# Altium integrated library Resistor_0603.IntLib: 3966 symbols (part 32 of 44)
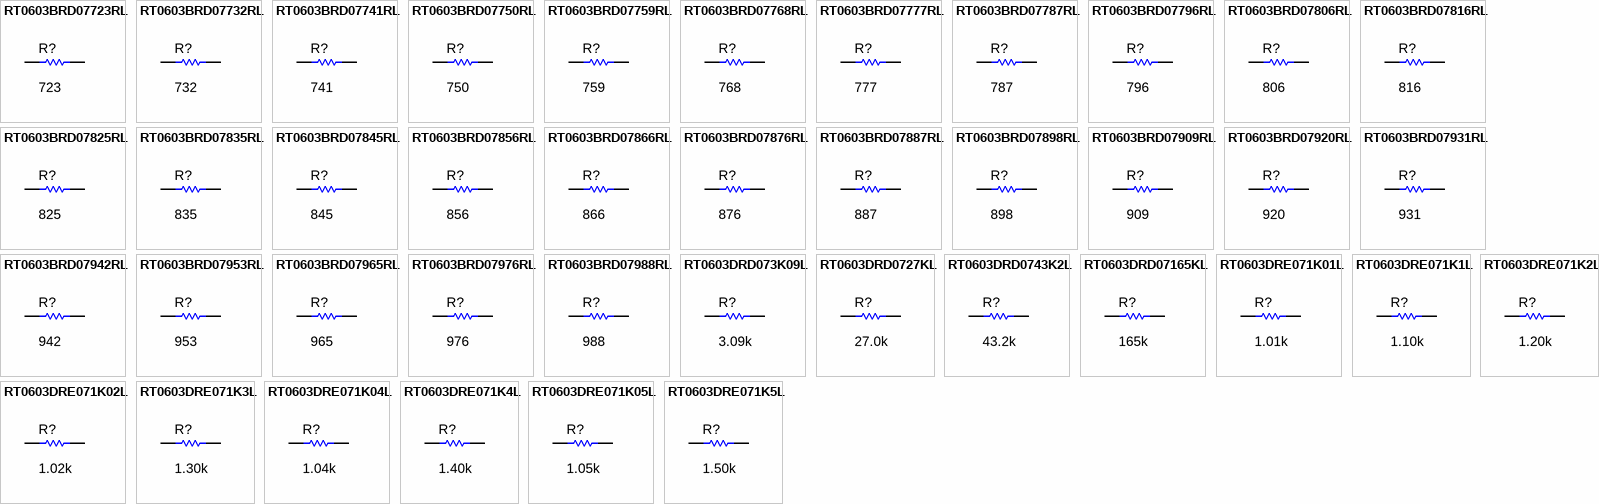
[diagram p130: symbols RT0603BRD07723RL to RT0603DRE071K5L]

## RT0603DRE071K02L
designator R?  ValueDisplayed: 1.02k  (hidden comment: RT0603DRE071K02L)
RES, 1.02 k, 0.5%, 0.1 W, 0603; Manufacturer: Yageo America; CompType: Resistor; Value: 1.02k; Res_ohm: 1020; Value_Code: 1k02; Tolerance_%: 0.5; Power_W: 0.1; Value2: 0.1W; VDC_V: 75; TempCo: 50 ppm/C; SizeArea_mm2: 1.28; SizeX_mm: 1.6; SizeY_mm: 0.8; SizeZ_mm: 1; EIA_Code: E192; U/M: EA; AEC Category: Q200
signal-integrity model Resistor
simulation model Resistor
footprint 0603
footprint 0603M
footprint 0603L
footprint 0603_HV
footprint 0603S
pins: 1, 2

## RT0603DRE071K2L
designator R?  ValueDisplayed: 1.20k  (hidden comment: RT0603DRE071K2L)
RES, 1.20 k, 0.5%, 0.1 W, 0603; Manufacturer: Yageo America; CompType: Resistor; Value: 1.20k; Res_ohm: 1200; Value_Code: 1k20; Tolerance_%: 0.5; Power_W: 0.1; Value2: 0.1W; VDC_V: 75; TempCo: 50 ppm/C; SizeArea_mm2: 1.28; SizeX_mm: 1.6; SizeY_mm: 0.8; SizeZ_mm: 1; EIA_Code: E192; U/M: EA; AEC Category: Q200
signal-integrity model Resistor
simulation model Resistor
footprint 0603
footprint 0603M
footprint 0603L
footprint 0603_HV
footprint 0603S
pins: 1, 2

## RT0603DRE071K3L
designator R?  ValueDisplayed: 1.30k  (hidden comment: RT0603DRE071K3L)
RES, 1.30 k, 0.5%, 0.1 W, 0603; Manufacturer: Yageo America; CompType: Resistor; Value: 1.30k; Res_ohm: 1300; Value_Code: 1k30; Tolerance_%: 0.5; Power_W: 0.1; Value2: 0.1W; VDC_V: 75; TempCo: 50 ppm/C; SizeArea_mm2: 1.28; SizeX_mm: 1.6; SizeY_mm: 0.8; SizeZ_mm: 1; EIA_Code: E192; U/M: EA; AEC Category: Q200
signal-integrity model Resistor
simulation model Resistor
footprint 0603
footprint 0603M
footprint 0603L
footprint 0603_HV
footprint 0603S
pins: 1, 2

## RT0603DRE071K04L
designator R?  ValueDisplayed: 1.04k  (hidden comment: RT0603DRE071K04L)
RES, 1.04 k, 0.5%, 0.1 W, 0603; Manufacturer: Yageo America; CompType: Resistor; Value: 1.04k; Res_ohm: 1040; Value_Code: 1k04; Tolerance_%: 0.5; Power_W: 0.1; Value2: 0.1W; VDC_V: 75; TempCo: 50 ppm/C; SizeArea_mm2: 1.28; SizeX_mm: 1.6; SizeY_mm: 0.8; SizeZ_mm: 1; EIA_Code: E192; U/M: EA; AEC Category: Q200
signal-integrity model Resistor
simulation model Resistor
footprint 0603
footprint 0603M
footprint 0603L
footprint 0603_HV
footprint 0603S
pins: 1, 2

## RT0603DRE071K4L
designator R?  ValueDisplayed: 1.40k  (hidden comment: RT0603DRE071K4L)
RES, 1.40 k, 0.5%, 0.1 W, 0603; Manufacturer: Yageo America; CompType: Resistor; Value: 1.40k; Res_ohm: 1400; Value_Code: 1k40; Tolerance_%: 0.5; Power_W: 0.1; Value2: 0.1W; VDC_V: 75; TempCo: 50 ppm/C; SizeArea_mm2: 1.28; SizeX_mm: 1.6; SizeY_mm: 0.8; SizeZ_mm: 1; EIA_Code: E192; U/M: EA; AEC Category: Q200
signal-integrity model Resistor
simulation model Resistor
footprint 0603
footprint 0603M
footprint 0603L
footprint 0603_HV
footprint 0603S
pins: 1, 2

## RT0603DRE071K05L
designator R?  ValueDisplayed: 1.05k  (hidden comment: RT0603DRE071K05L)
RES, 1.05 k, 0.5%, 0.1 W, 0603; Manufacturer: Yageo America; CompType: Resistor; Value: 1.05k; Res_ohm: 1050; Value_Code: 1k05; Tolerance_%: 0.5; Power_W: 0.1; Value2: 0.1W; VDC_V: 75; TempCo: 50 ppm/C; SizeArea_mm2: 1.28; SizeX_mm: 1.6; SizeY_mm: 0.8; SizeZ_mm: 1; EIA_Code: E192; U/M: EA; AEC Category: Q200
signal-integrity model Resistor
simulation model Resistor
footprint 0603
footprint 0603M
footprint 0603L
footprint 0603_HV
footprint 0603S
pins: 1, 2

## RT0603DRE071K5L
designator R?  ValueDisplayed: 1.50k  (hidden comment: RT0603DRE071K5L)
RES, 1.50 k, 0.5%, 0.1 W, 0603; Manufacturer: Yageo America; CompType: Resistor; Value: 1.50k; Res_ohm: 1500; Value_Code: 1k50; Tolerance_%: 0.5; Power_W: 0.1; Value2: 0.1W; VDC_V: 75; TempCo: 50 ppm/C; SizeArea_mm2: 1.28; SizeX_mm: 1.6; SizeY_mm: 0.8; SizeZ_mm: 1; EIA_Code: E192; U/M: EA; AEC Category: Q200
signal-integrity model Resistor
simulation model Resistor
footprint 0603
footprint 0603M
footprint 0603L
footprint 0603_HV
footprint 0603S
pins: 1, 2

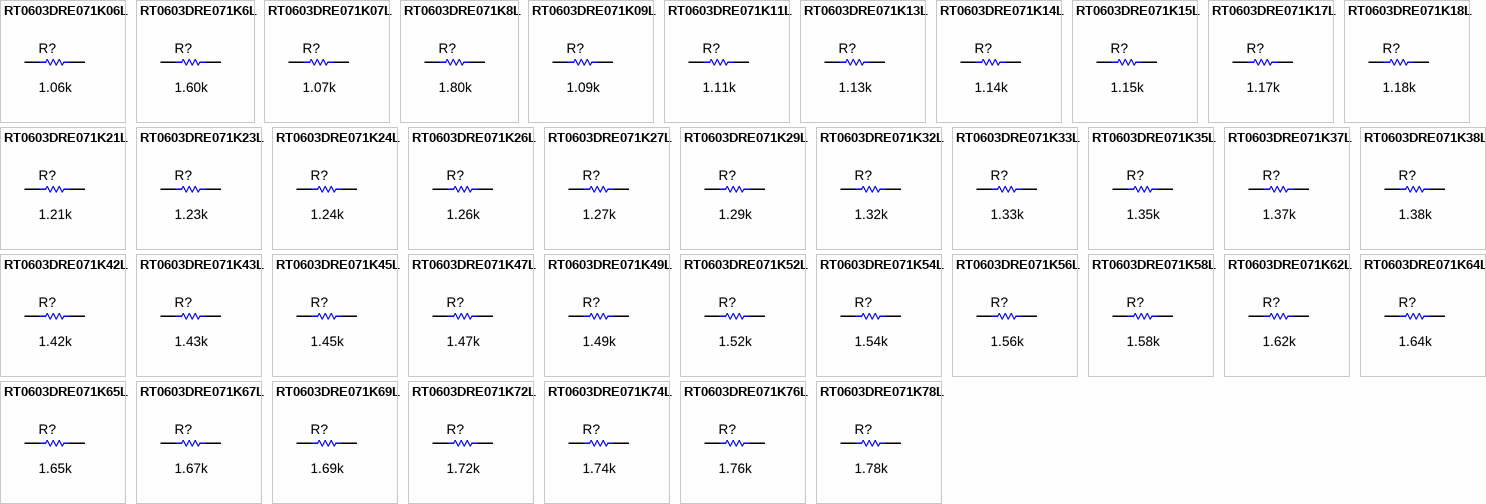
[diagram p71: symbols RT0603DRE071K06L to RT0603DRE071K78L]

## RT0603DRE071K06L
designator R?  ValueDisplayed: 1.06k  (hidden comment: RT0603DRE071K06L)
RES, 1.06 k, 0.5%, 0.1 W, 0603; Manufacturer: Yageo America; CompType: Resistor; Value: 1.06k; Res_ohm: 1060; Value_Code: 1k06; Tolerance_%: 0.5; Power_W: 0.1; Value2: 0.1W; VDC_V: 75; TempCo: 50 ppm/C; SizeArea_mm2: 1.28; SizeX_mm: 1.6; SizeY_mm: 0.8; SizeZ_mm: 1; EIA_Code: E192; U/M: EA; AEC Category: Q200
signal-integrity model Resistor
simulation model Resistor
footprint 0603
footprint 0603M
footprint 0603L
footprint 0603_HV
footprint 0603S
pins: 1, 2

## RT0603DRE071K6L
designator R?  ValueDisplayed: 1.60k  (hidden comment: RT0603DRE071K6L)
RES, 1.60 k, 0.5%, 0.1 W, 0603; Manufacturer: Yageo America; CompType: Resistor; Value: 1.60k; Res_ohm: 1600; Value_Code: 1k60; Tolerance_%: 0.5; Power_W: 0.1; Value2: 0.1W; VDC_V: 75; TempCo: 50 ppm/C; SizeArea_mm2: 1.28; SizeX_mm: 1.6; SizeY_mm: 0.8; SizeZ_mm: 1; EIA_Code: E192; U/M: EA; AEC Category: Q200
signal-integrity model Resistor
simulation model Resistor
footprint 0603
footprint 0603M
footprint 0603L
footprint 0603_HV
footprint 0603S
pins: 1, 2

## RT0603DRE071K07L
designator R?  ValueDisplayed: 1.07k  (hidden comment: RT0603DRE071K07L)
RES, 1.07 k, 0.5%, 0.1 W, 0603; Manufacturer: Yageo America; CompType: Resistor; Value: 1.07k; Res_ohm: 1070; Value_Code: 1k07; Tolerance_%: 0.5; Power_W: 0.1; Value2: 0.1W; VDC_V: 75; TempCo: 50 ppm/C; SizeArea_mm2: 1.28; SizeX_mm: 1.6; SizeY_mm: 0.8; SizeZ_mm: 1; EIA_Code: E192; U/M: EA; AEC Category: Q200
signal-integrity model Resistor
simulation model Resistor
footprint 0603
footprint 0603M
footprint 0603L
footprint 0603_HV
footprint 0603S
pins: 1, 2

## RT0603DRE071K8L
designator R?  ValueDisplayed: 1.80k  (hidden comment: RT0603DRE071K8L)
RES, 1.80 k, 0.5%, 0.1 W, 0603; Manufacturer: Yageo America; CompType: Resistor; Value: 1.80k; Res_ohm: 1800; Value_Code: 1k80; Tolerance_%: 0.5; Power_W: 0.1; Value2: 0.1W; VDC_V: 75; TempCo: 50 ppm/C; SizeArea_mm2: 1.28; SizeX_mm: 1.6; SizeY_mm: 0.8; SizeZ_mm: 1; EIA_Code: E192; U/M: EA; AEC Category: Q200
signal-integrity model Resistor
simulation model Resistor
footprint 0603
footprint 0603M
footprint 0603L
footprint 0603_HV
footprint 0603S
pins: 1, 2

## RT0603DRE071K09L
designator R?  ValueDisplayed: 1.09k  (hidden comment: RT0603DRE071K09L)
RES, 1.09 k, 0.5%, 0.1 W, 0603; Manufacturer: Yageo America; CompType: Resistor; Value: 1.09k; Res_ohm: 1090; Value_Code: 1k09; Tolerance_%: 0.5; Power_W: 0.1; Value2: 0.1W; VDC_V: 75; TempCo: 50 ppm/C; SizeArea_mm2: 1.28; SizeX_mm: 1.6; SizeY_mm: 0.8; SizeZ_mm: 1; EIA_Code: E192; U/M: EA; AEC Category: Q200
signal-integrity model Resistor
simulation model Resistor
footprint 0603
footprint 0603M
footprint 0603L
footprint 0603_HV
footprint 0603S
pins: 1, 2

## RT0603DRE071K11L
designator R?  ValueDisplayed: 1.11k  (hidden comment: RT0603DRE071K11L)
RES, 1.11 k, 0.5%, 0.1 W, 0603; Manufacturer: Yageo America; CompType: Resistor; Value: 1.11k; Res_ohm: 1110; Value_Code: 1k11; Tolerance_%: 0.5; Power_W: 0.1; Value2: 0.1W; VDC_V: 75; TempCo: 50 ppm/C; SizeArea_mm2: 1.28; SizeX_mm: 1.6; SizeY_mm: 0.8; SizeZ_mm: 1; EIA_Code: E192; U/M: EA; AEC Category: Q200
signal-integrity model Resistor
simulation model Resistor
footprint 0603
footprint 0603M
footprint 0603L
footprint 0603_HV
footprint 0603S
pins: 1, 2

## RT0603DRE071K13L
designator R?  ValueDisplayed: 1.13k  (hidden comment: RT0603DRE071K13L)
RES, 1.13 k, 0.5%, 0.1 W, 0603; Manufacturer: Yageo America; CompType: Resistor; Value: 1.13k; Res_ohm: 1130; Value_Code: 1k13; Tolerance_%: 0.5; Power_W: 0.1; Value2: 0.1W; VDC_V: 75; TempCo: 50 ppm/C; SizeArea_mm2: 1.28; SizeX_mm: 1.6; SizeY_mm: 0.8; SizeZ_mm: 1; EIA_Code: E192; U/M: EA; AEC Category: Q200
signal-integrity model Resistor
simulation model Resistor
footprint 0603
footprint 0603M
footprint 0603L
footprint 0603_HV
footprint 0603S
pins: 1, 2

## RT0603DRE071K14L
designator R?  ValueDisplayed: 1.14k  (hidden comment: RT0603DRE071K14L)
RES, 1.14 k, 0.5%, 0.1 W, 0603; Manufacturer: Yageo America; CompType: Resistor; Value: 1.14k; Res_ohm: 1140; Value_Code: 1k14; Tolerance_%: 0.5; Power_W: 0.1; Value2: 0.1W; VDC_V: 75; TempCo: 50 ppm/C; SizeArea_mm2: 1.28; SizeX_mm: 1.6; SizeY_mm: 0.8; SizeZ_mm: 1; EIA_Code: E192; U/M: EA; AEC Category: Q200
signal-integrity model Resistor
simulation model Resistor
footprint 0603
footprint 0603M
footprint 0603L
footprint 0603_HV
footprint 0603S
pins: 1, 2

## RT0603DRE071K15L
designator R?  ValueDisplayed: 1.15k  (hidden comment: RT0603DRE071K15L)
RES, 1.15 k, 0.5%, 0.1 W, 0603; Manufacturer: Yageo America; CompType: Resistor; Value: 1.15k; Res_ohm: 1150; Value_Code: 1k15; Tolerance_%: 0.5; Power_W: 0.1; Value2: 0.1W; VDC_V: 75; TempCo: 50 ppm/C; SizeArea_mm2: 1.28; SizeX_mm: 1.6; SizeY_mm: 0.8; SizeZ_mm: 1; EIA_Code: E192; U/M: EA; AEC Category: Q200
signal-integrity model Resistor
simulation model Resistor
footprint 0603
footprint 0603M
footprint 0603L
footprint 0603_HV
footprint 0603S
pins: 1, 2

## RT0603DRE071K17L
designator R?  ValueDisplayed: 1.17k  (hidden comment: RT0603DRE071K17L)
RES, 1.17 k, 0.5%, 0.1 W, 0603; Manufacturer: Yageo America; CompType: Resistor; Value: 1.17k; Res_ohm: 1170; Value_Code: 1k17; Tolerance_%: 0.5; Power_W: 0.1; Value2: 0.1W; VDC_V: 75; TempCo: 50 ppm/C; SizeArea_mm2: 1.28; SizeX_mm: 1.6; SizeY_mm: 0.8; SizeZ_mm: 1; EIA_Code: E192; U/M: EA; AEC Category: Q200
signal-integrity model Resistor
simulation model Resistor
footprint 0603
footprint 0603M
footprint 0603L
footprint 0603_HV
footprint 0603S
pins: 1, 2

## RT0603DRE071K18L
designator R?  ValueDisplayed: 1.18k  (hidden comment: RT0603DRE071K18L)
RES, 1.18 k, 0.5%, 0.1 W, 0603; Manufacturer: Yageo America; CompType: Resistor; Value: 1.18k; Res_ohm: 1180; Value_Code: 1k18; Tolerance_%: 0.5; Power_W: 0.1; Value2: 0.1W; VDC_V: 75; TempCo: 50 ppm/C; SizeArea_mm2: 1.28; SizeX_mm: 1.6; SizeY_mm: 0.8; SizeZ_mm: 1; EIA_Code: E192; U/M: EA; AEC Category: Q200
signal-integrity model Resistor
simulation model Resistor
footprint 0603
footprint 0603M
footprint 0603L
footprint 0603_HV
footprint 0603S
pins: 1, 2

## RT0603DRE071K21L
designator R?  ValueDisplayed: 1.21k  (hidden comment: RT0603DRE071K21L)
RES, 1.21 k, 0.5%, 0.1 W, 0603; Manufacturer: Yageo America; CompType: Resistor; Value: 1.21k; Res_ohm: 1210; Value_Code: 1k21; Tolerance_%: 0.5; Power_W: 0.1; Value2: 0.1W; VDC_V: 75; TempCo: 50 ppm/C; SizeArea_mm2: 1.28; SizeX_mm: 1.6; SizeY_mm: 0.8; SizeZ_mm: 1; EIA_Code: E192; U/M: EA; AEC Category: Q200
signal-integrity model Resistor
simulation model Resistor
footprint 0603
footprint 0603M
footprint 0603L
footprint 0603_HV
footprint 0603S
pins: 1, 2

## RT0603DRE071K23L
designator R?  ValueDisplayed: 1.23k  (hidden comment: RT0603DRE071K23L)
RES, 1.23 k, 0.5%, 0.1 W, 0603; Manufacturer: Yageo America; CompType: Resistor; Value: 1.23k; Res_ohm: 1230; Value_Code: 1k23; Tolerance_%: 0.5; Power_W: 0.1; Value2: 0.1W; VDC_V: 75; TempCo: 50 ppm/C; SizeArea_mm2: 1.28; SizeX_mm: 1.6; SizeY_mm: 0.8; SizeZ_mm: 1; EIA_Code: E192; U/M: EA; AEC Category: Q200
signal-integrity model Resistor
simulation model Resistor
footprint 0603
footprint 0603M
footprint 0603L
footprint 0603_HV
footprint 0603S
pins: 1, 2

## RT0603DRE071K24L
designator R?  ValueDisplayed: 1.24k  (hidden comment: RT0603DRE071K24L)
RES, 1.24 k, 0.5%, 0.1 W, 0603; Manufacturer: Yageo America; CompType: Resistor; Value: 1.24k; Res_ohm: 1240; Value_Code: 1k24; Tolerance_%: 0.5; Power_W: 0.1; Value2: 0.1W; VDC_V: 75; TempCo: 50 ppm/C; SizeArea_mm2: 1.28; SizeX_mm: 1.6; SizeY_mm: 0.8; SizeZ_mm: 1; EIA_Code: E192; U/M: EA; AEC Category: Q200
signal-integrity model Resistor
simulation model Resistor
footprint 0603
footprint 0603M
footprint 0603L
footprint 0603_HV
footprint 0603S
pins: 1, 2

## RT0603DRE071K26L
designator R?  ValueDisplayed: 1.26k  (hidden comment: RT0603DRE071K26L)
RES, 1.26 k, 0.5%, 0.1 W, 0603; Manufacturer: Yageo America; CompType: Resistor; Value: 1.26k; Res_ohm: 1260; Value_Code: 1k26; Tolerance_%: 0.5; Power_W: 0.1; Value2: 0.1W; VDC_V: 75; TempCo: 50 ppm/C; SizeArea_mm2: 1.28; SizeX_mm: 1.6; SizeY_mm: 0.8; SizeZ_mm: 1; EIA_Code: E192; U/M: EA; AEC Category: Q200
signal-integrity model Resistor
simulation model Resistor
footprint 0603
footprint 0603M
footprint 0603L
footprint 0603_HV
footprint 0603S
pins: 1, 2

## RT0603DRE071K27L
designator R?  ValueDisplayed: 1.27k  (hidden comment: RT0603DRE071K27L)
RES, 1.27 k, 0.5%, 0.1 W, 0603; Manufacturer: Yageo America; CompType: Resistor; Value: 1.27k; Res_ohm: 1270; Value_Code: 1k27; Tolerance_%: 0.5; Power_W: 0.1; Value2: 0.1W; VDC_V: 75; TempCo: 50 ppm/C; SizeArea_mm2: 1.28; SizeX_mm: 1.6; SizeY_mm: 0.8; SizeZ_mm: 1; EIA_Code: E192; U/M: EA; AEC Category: Q200
signal-integrity model Resistor
simulation model Resistor
footprint 0603
footprint 0603M
footprint 0603L
footprint 0603_HV
footprint 0603S
pins: 1, 2

## RT0603DRE071K29L
designator R?  ValueDisplayed: 1.29k  (hidden comment: RT0603DRE071K29L)
RES, 1.29 k, 0.5%, 0.1 W, 0603; Manufacturer: Yageo America; CompType: Resistor; Value: 1.29k; Res_ohm: 1290; Value_Code: 1k29; Tolerance_%: 0.5; Power_W: 0.1; Value2: 0.1W; VDC_V: 75; TempCo: 50 ppm/C; SizeArea_mm2: 1.28; SizeX_mm: 1.6; SizeY_mm: 0.8; SizeZ_mm: 1; EIA_Code: E192; U/M: EA; AEC Category: Q200
signal-integrity model Resistor
simulation model Resistor
footprint 0603
footprint 0603M
footprint 0603L
footprint 0603_HV
footprint 0603S
pins: 1, 2

## RT0603DRE071K32L
designator R?  ValueDisplayed: 1.32k  (hidden comment: RT0603DRE071K32L)
RES, 1.32 k, 0.5%, 0.1 W, 0603; Manufacturer: Yageo America; CompType: Resistor; Value: 1.32k; Res_ohm: 1320; Value_Code: 1k32; Tolerance_%: 0.5; Power_W: 0.1; Value2: 0.1W; VDC_V: 75; TempCo: 50 ppm/C; SizeArea_mm2: 1.28; SizeX_mm: 1.6; SizeY_mm: 0.8; SizeZ_mm: 1; EIA_Code: E192; U/M: EA; AEC Category: Q200
signal-integrity model Resistor
simulation model Resistor
footprint 0603
footprint 0603M
footprint 0603L
footprint 0603_HV
footprint 0603S
pins: 1, 2

## RT0603DRE071K33L
designator R?  ValueDisplayed: 1.33k  (hidden comment: RT0603DRE071K33L)
RES, 1.33 k, 0.5%, 0.1 W, 0603; Manufacturer: Yageo America; CompType: Resistor; Value: 1.33k; Res_ohm: 1330; Value_Code: 1k33; Tolerance_%: 0.5; Power_W: 0.1; Value2: 0.1W; VDC_V: 75; TempCo: 50 ppm/C; SizeArea_mm2: 1.28; SizeX_mm: 1.6; SizeY_mm: 0.8; SizeZ_mm: 1; EIA_Code: E192; U/M: EA; AEC Category: Q200
signal-integrity model Resistor
simulation model Resistor
footprint 0603
footprint 0603M
footprint 0603L
footprint 0603_HV
footprint 0603S
pins: 1, 2

## RT0603DRE071K35L
designator R?  ValueDisplayed: 1.35k  (hidden comment: RT0603DRE071K35L)
RES, 1.35 k, 0.5%, 0.1 W, 0603; Manufacturer: Yageo America; CompType: Resistor; Value: 1.35k; Res_ohm: 1350; Value_Code: 1k35; Tolerance_%: 0.5; Power_W: 0.1; Value2: 0.1W; VDC_V: 75; TempCo: 50 ppm/C; SizeArea_mm2: 1.28; SizeX_mm: 1.6; SizeY_mm: 0.8; SizeZ_mm: 1; EIA_Code: E192; U/M: EA; AEC Category: Q200
signal-integrity model Resistor
simulation model Resistor
footprint 0603
footprint 0603M
footprint 0603L
footprint 0603_HV
footprint 0603S
pins: 1, 2

## RT0603DRE071K37L
designator R?  ValueDisplayed: 1.37k  (hidden comment: RT0603DRE071K37L)
RES, 1.37 k, 0.5%, 0.1 W, 0603; Manufacturer: Yageo America; CompType: Resistor; Value: 1.37k; Res_ohm: 1370; Value_Code: 1k37; Tolerance_%: 0.5; Power_W: 0.1; Value2: 0.1W; VDC_V: 75; TempCo: 50 ppm/C; SizeArea_mm2: 1.28; SizeX_mm: 1.6; SizeY_mm: 0.8; SizeZ_mm: 1; EIA_Code: E192; U/M: EA; AEC Category: Q200
signal-integrity model Resistor
simulation model Resistor
footprint 0603
footprint 0603M
footprint 0603L
footprint 0603_HV
footprint 0603S
pins: 1, 2

## RT0603DRE071K38L
designator R?  ValueDisplayed: 1.38k  (hidden comment: RT0603DRE071K38L)
RES, 1.38 k, 0.5%, 0.1 W, 0603; Manufacturer: Yageo America; CompType: Resistor; Value: 1.38k; Res_ohm: 1380; Value_Code: 1k38; Tolerance_%: 0.5; Power_W: 0.1; Value2: 0.1W; VDC_V: 75; TempCo: 50 ppm/C; SizeArea_mm2: 1.28; SizeX_mm: 1.6; SizeY_mm: 0.8; SizeZ_mm: 1; EIA_Code: E192; U/M: EA; AEC Category: Q200
signal-integrity model Resistor
simulation model Resistor
footprint 0603
footprint 0603M
footprint 0603L
footprint 0603_HV
footprint 0603S
pins: 1, 2

## RT0603DRE071K42L
designator R?  ValueDisplayed: 1.42k  (hidden comment: RT0603DRE071K42L)
RES, 1.42 k, 0.5%, 0.1 W, 0603; Manufacturer: Yageo America; CompType: Resistor; Value: 1.42k; Res_ohm: 1420; Value_Code: 1k42; Tolerance_%: 0.5; Power_W: 0.1; Value2: 0.1W; VDC_V: 75; TempCo: 50 ppm/C; SizeArea_mm2: 1.28; SizeX_mm: 1.6; SizeY_mm: 0.8; SizeZ_mm: 1; EIA_Code: E192; U/M: EA; AEC Category: Q200
signal-integrity model Resistor
simulation model Resistor
footprint 0603
footprint 0603M
footprint 0603L
footprint 0603_HV
footprint 0603S
pins: 1, 2

## RT0603DRE071K43L
designator R?  ValueDisplayed: 1.43k  (hidden comment: RT0603DRE071K43L)
RES, 1.43 k, 0.5%, 0.1 W, 0603; Manufacturer: Yageo America; CompType: Resistor; Value: 1.43k; Res_ohm: 1430; Value_Code: 1k43; Tolerance_%: 0.5; Power_W: 0.1; Value2: 0.1W; VDC_V: 75; TempCo: 50 ppm/C; SizeArea_mm2: 1.28; SizeX_mm: 1.6; SizeY_mm: 0.8; SizeZ_mm: 1; EIA_Code: E192; U/M: EA; AEC Category: Q200
signal-integrity model Resistor
simulation model Resistor
footprint 0603
footprint 0603M
footprint 0603L
footprint 0603_HV
footprint 0603S
pins: 1, 2

## RT0603DRE071K45L
designator R?  ValueDisplayed: 1.45k  (hidden comment: RT0603DRE071K45L)
RES, 1.45 k, 0.5%, 0.1 W, 0603; Manufacturer: Yageo America; CompType: Resistor; Value: 1.45k; Res_ohm: 1450; Value_Code: 1k45; Tolerance_%: 0.5; Power_W: 0.1; Value2: 0.1W; VDC_V: 75; TempCo: 50 ppm/C; SizeArea_mm2: 1.28; SizeX_mm: 1.6; SizeY_mm: 0.8; SizeZ_mm: 1; EIA_Code: E192; U/M: EA; AEC Category: Q200
signal-integrity model Resistor
simulation model Resistor
footprint 0603
footprint 0603M
footprint 0603L
footprint 0603_HV
footprint 0603S
pins: 1, 2

## RT0603DRE071K47L
designator R?  ValueDisplayed: 1.47k  (hidden comment: RT0603DRE071K47L)
RES, 1.47 k, 0.5%, 0.1 W, 0603; Manufacturer: Yageo America; CompType: Resistor; Value: 1.47k; Res_ohm: 1470; Value_Code: 1k47; Tolerance_%: 0.5; Power_W: 0.1; Value2: 0.1W; VDC_V: 75; TempCo: 50 ppm/C; SizeArea_mm2: 1.28; SizeX_mm: 1.6; SizeY_mm: 0.8; SizeZ_mm: 1; EIA_Code: E192; U/M: EA; AEC Category: Q200
signal-integrity model Resistor
simulation model Resistor
footprint 0603
footprint 0603M
footprint 0603L
footprint 0603_HV
footprint 0603S
pins: 1, 2

## RT0603DRE071K49L
designator R?  ValueDisplayed: 1.49k  (hidden comment: RT0603DRE071K49L)
RES, 1.49 k, 0.5%, 0.1 W, 0603; Manufacturer: Yageo America; CompType: Resistor; Value: 1.49k; Res_ohm: 1490; Value_Code: 1k49; Tolerance_%: 0.5; Power_W: 0.1; Value2: 0.1W; VDC_V: 75; TempCo: 50 ppm/C; SizeArea_mm2: 1.28; SizeX_mm: 1.6; SizeY_mm: 0.8; SizeZ_mm: 1; EIA_Code: E192; U/M: EA; AEC Category: Q200
signal-integrity model Resistor
simulation model Resistor
footprint 0603
footprint 0603M
footprint 0603L
footprint 0603_HV
footprint 0603S
pins: 1, 2

## RT0603DRE071K52L
designator R?  ValueDisplayed: 1.52k  (hidden comment: RT0603DRE071K52L)
RES, 1.52 k, 0.5%, 0.1 W, 0603; Manufacturer: Yageo America; CompType: Resistor; Value: 1.52k; Res_ohm: 1520; Value_Code: 1k52; Tolerance_%: 0.5; Power_W: 0.1; Value2: 0.1W; VDC_V: 75; TempCo: 50 ppm/C; SizeArea_mm2: 1.28; SizeX_mm: 1.6; SizeY_mm: 0.8; SizeZ_mm: 1; EIA_Code: E192; U/M: EA; AEC Category: Q200
signal-integrity model Resistor
simulation model Resistor
footprint 0603
footprint 0603M
footprint 0603L
footprint 0603_HV
footprint 0603S
pins: 1, 2

## RT0603DRE071K54L
designator R?  ValueDisplayed: 1.54k  (hidden comment: RT0603DRE071K54L)
RES, 1.54 k, 0.5%, 0.1 W, 0603; Manufacturer: Yageo America; CompType: Resistor; Value: 1.54k; Res_ohm: 1540; Value_Code: 1k54; Tolerance_%: 0.5; Power_W: 0.1; Value2: 0.1W; VDC_V: 75; TempCo: 50 ppm/C; SizeArea_mm2: 1.28; SizeX_mm: 1.6; SizeY_mm: 0.8; SizeZ_mm: 1; EIA_Code: E192; U/M: EA; AEC Category: Q200
signal-integrity model Resistor
simulation model Resistor
footprint 0603
footprint 0603M
footprint 0603L
footprint 0603_HV
footprint 0603S
pins: 1, 2

## RT0603DRE071K56L
designator R?  ValueDisplayed: 1.56k  (hidden comment: RT0603DRE071K56L)
RES, 1.56 k, 0.5%, 0.1 W, 0603; Manufacturer: Yageo America; CompType: Resistor; Value: 1.56k; Res_ohm: 1560; Value_Code: 1k56; Tolerance_%: 0.5; Power_W: 0.1; Value2: 0.1W; VDC_V: 75; TempCo: 50 ppm/C; SizeArea_mm2: 1.28; SizeX_mm: 1.6; SizeY_mm: 0.8; SizeZ_mm: 1; EIA_Code: E192; U/M: EA; AEC Category: Q200
signal-integrity model Resistor
simulation model Resistor
footprint 0603
footprint 0603M
footprint 0603L
footprint 0603_HV
footprint 0603S
pins: 1, 2

## RT0603DRE071K58L
designator R?  ValueDisplayed: 1.58k  (hidden comment: RT0603DRE071K58L)
RES, 1.58 k, 0.5%, 0.1 W, 0603; Manufacturer: Yageo America; CompType: Resistor; Value: 1.58k; Res_ohm: 1580; Value_Code: 1k58; Tolerance_%: 0.5; Power_W: 0.1; Value2: 0.1W; VDC_V: 75; TempCo: 50 ppm/C; SizeArea_mm2: 1.28; SizeX_mm: 1.6; SizeY_mm: 0.8; SizeZ_mm: 1; EIA_Code: E192; U/M: EA; AEC Category: Q200
signal-integrity model Resistor
simulation model Resistor
footprint 0603
footprint 0603M
footprint 0603L
footprint 0603_HV
footprint 0603S
pins: 1, 2

## RT0603DRE071K62L
designator R?  ValueDisplayed: 1.62k  (hidden comment: RT0603DRE071K62L)
RES, 1.62 k, 0.5%, 0.1 W, 0603; Manufacturer: Yageo America; CompType: Resistor; Value: 1.62k; Res_ohm: 1620; Value_Code: 1k62; Tolerance_%: 0.5; Power_W: 0.1; Value2: 0.1W; VDC_V: 75; TempCo: 50 ppm/C; SizeArea_mm2: 1.28; SizeX_mm: 1.6; SizeY_mm: 0.8; SizeZ_mm: 1; EIA_Code: E192; U/M: EA; AEC Category: Q200
signal-integrity model Resistor
simulation model Resistor
footprint 0603
footprint 0603M
footprint 0603L
footprint 0603_HV
footprint 0603S
pins: 1, 2

## RT0603DRE071K64L
designator R?  ValueDisplayed: 1.64k  (hidden comment: RT0603DRE071K64L)
RES, 1.64 k, 0.5%, 0.1 W, 0603; Manufacturer: Yageo America; CompType: Resistor; Value: 1.64k; Res_ohm: 1640; Value_Code: 1k64; Tolerance_%: 0.5; Power_W: 0.1; Value2: 0.1W; VDC_V: 75; TempCo: 50 ppm/C; SizeArea_mm2: 1.28; SizeX_mm: 1.6; SizeY_mm: 0.8; SizeZ_mm: 1; EIA_Code: E192; U/M: EA; AEC Category: Q200
signal-integrity model Resistor
simulation model Resistor
footprint 0603
footprint 0603M
footprint 0603L
footprint 0603_HV
footprint 0603S
pins: 1, 2

## RT0603DRE071K65L
designator R?  ValueDisplayed: 1.65k  (hidden comment: RT0603DRE071K65L)
RES, 1.65 k, 0.5%, 0.1 W, 0603; Manufacturer: Yageo America; CompType: Resistor; Value: 1.65k; Res_ohm: 1650; Value_Code: 1k65; Tolerance_%: 0.5; Power_W: 0.1; Value2: 0.1W; VDC_V: 75; TempCo: 50 ppm/C; SizeArea_mm2: 1.28; SizeX_mm: 1.6; SizeY_mm: 0.8; SizeZ_mm: 1; EIA_Code: E192; U/M: EA; AEC Category: Q200
signal-integrity model Resistor
simulation model Resistor
footprint 0603
footprint 0603M
footprint 0603L
footprint 0603_HV
footprint 0603S
pins: 1, 2

## RT0603DRE071K67L
designator R?  ValueDisplayed: 1.67k  (hidden comment: RT0603DRE071K67L)
RES, 1.67 k, 0.5%, 0.1 W, 0603; Manufacturer: Yageo America; CompType: Resistor; Value: 1.67k; Res_ohm: 1670; Value_Code: 1k67; Tolerance_%: 0.5; Power_W: 0.1; Value2: 0.1W; VDC_V: 75; TempCo: 50 ppm/C; SizeArea_mm2: 1.28; SizeX_mm: 1.6; SizeY_mm: 0.8; SizeZ_mm: 1; EIA_Code: E192; U/M: EA; AEC Category: Q200
signal-integrity model Resistor
simulation model Resistor
footprint 0603
footprint 0603M
footprint 0603L
footprint 0603_HV
footprint 0603S
pins: 1, 2

## RT0603DRE071K69L
designator R?  ValueDisplayed: 1.69k  (hidden comment: RT0603DRE071K69L)
RES, 1.69 k, 0.5%, 0.1 W, 0603; Manufacturer: Yageo America; CompType: Resistor; Value: 1.69k; Res_ohm: 1690; Value_Code: 1k69; Tolerance_%: 0.5; Power_W: 0.1; Value2: 0.1W; VDC_V: 75; TempCo: 50 ppm/C; SizeArea_mm2: 1.28; SizeX_mm: 1.6; SizeY_mm: 0.8; SizeZ_mm: 1; EIA_Code: E192; U/M: EA; AEC Category: Q200
signal-integrity model Resistor
simulation model Resistor
footprint 0603
footprint 0603M
footprint 0603L
footprint 0603_HV
footprint 0603S
pins: 1, 2

## RT0603DRE071K72L
designator R?  ValueDisplayed: 1.72k  (hidden comment: RT0603DRE071K72L)
RES, 1.72 k, 0.5%, 0.1 W, 0603; Manufacturer: Yageo America; CompType: Resistor; Value: 1.72k; Res_ohm: 1720; Value_Code: 1k72; Tolerance_%: 0.5; Power_W: 0.1; Value2: 0.1W; VDC_V: 75; TempCo: 50 ppm/C; SizeArea_mm2: 1.28; SizeX_mm: 1.6; SizeY_mm: 0.8; SizeZ_mm: 1; EIA_Code: E192; U/M: EA; AEC Category: Q200
signal-integrity model Resistor
simulation model Resistor
footprint 0603
footprint 0603M
footprint 0603L
footprint 0603_HV
footprint 0603S
pins: 1, 2

## RT0603DRE071K74L
designator R?  ValueDisplayed: 1.74k  (hidden comment: RT0603DRE071K74L)
RES, 1.74 k, 0.5%, 0.1 W, 0603; Manufacturer: Yageo America; CompType: Resistor; Value: 1.74k; Res_ohm: 1740; Value_Code: 1k74; Tolerance_%: 0.5; Power_W: 0.1; Value2: 0.1W; VDC_V: 75; TempCo: 50 ppm/C; SizeArea_mm2: 1.28; SizeX_mm: 1.6; SizeY_mm: 0.8; SizeZ_mm: 1; EIA_Code: E192; U/M: EA; AEC Category: Q200
signal-integrity model Resistor
simulation model Resistor
footprint 0603
footprint 0603M
footprint 0603L
footprint 0603_HV
footprint 0603S
pins: 1, 2

## RT0603DRE071K76L
designator R?  ValueDisplayed: 1.76k  (hidden comment: RT0603DRE071K76L)
RES, 1.76 k, 0.5%, 0.1 W, 0603; Manufacturer: Yageo America; CompType: Resistor; Value: 1.76k; Res_ohm: 1760; Value_Code: 1k76; Tolerance_%: 0.5; Power_W: 0.1; Value2: 0.1W; VDC_V: 75; TempCo: 50 ppm/C; SizeArea_mm2: 1.28; SizeX_mm: 1.6; SizeY_mm: 0.8; SizeZ_mm: 1; EIA_Code: E192; U/M: EA; AEC Category: Q200
signal-integrity model Resistor
simulation model Resistor
footprint 0603
footprint 0603M
footprint 0603L
footprint 0603_HV
footprint 0603S
pins: 1, 2

## RT0603DRE071K78L
designator R?  ValueDisplayed: 1.78k  (hidden comment: RT0603DRE071K78L)
RES, 1.78 k, 0.5%, 0.1 W, 0603; Manufacturer: Yageo America; CompType: Resistor; Value: 1.78k; Res_ohm: 1780; Value_Code: 1k78; Tolerance_%: 0.5; Power_W: 0.1; Value2: 0.1W; VDC_V: 75; TempCo: 50 ppm/C; SizeArea_mm2: 1.28; SizeX_mm: 1.6; SizeY_mm: 0.8; SizeZ_mm: 1; EIA_Code: E192; U/M: EA; AEC Category: Q200
signal-integrity model Resistor
simulation model Resistor
footprint 0603
footprint 0603M
footprint 0603L
footprint 0603_HV
footprint 0603S
pins: 1, 2

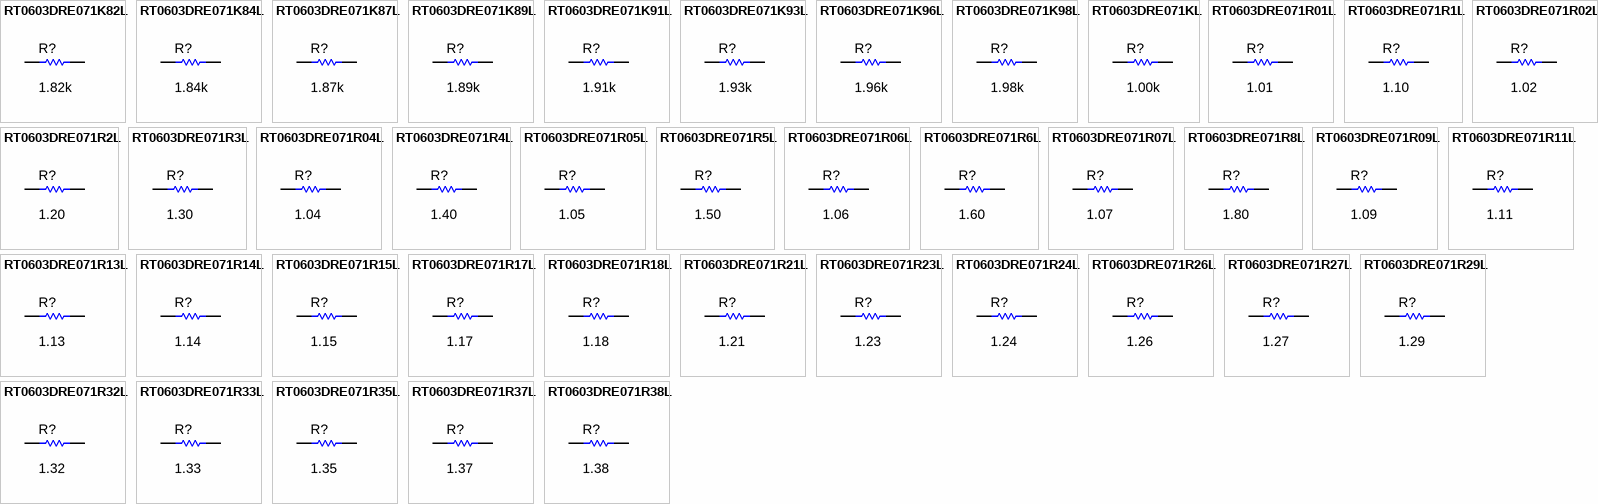
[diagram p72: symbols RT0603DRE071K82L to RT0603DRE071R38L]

## RT0603DRE071K82L
designator R?  ValueDisplayed: 1.82k  (hidden comment: RT0603DRE071K82L)
RES, 1.82 k, 0.5%, 0.1 W, 0603; Manufacturer: Yageo America; CompType: Resistor; Value: 1.82k; Res_ohm: 1820; Value_Code: 1k82; Tolerance_%: 0.5; Power_W: 0.1; Value2: 0.1W; VDC_V: 75; TempCo: 50 ppm/C; SizeArea_mm2: 1.28; SizeX_mm: 1.6; SizeY_mm: 0.8; SizeZ_mm: 1; EIA_Code: E192; U/M: EA; AEC Category: Q200
signal-integrity model Resistor
simulation model Resistor
footprint 0603
footprint 0603M
footprint 0603L
footprint 0603_HV
footprint 0603S
pins: 1, 2

## RT0603DRE071K84L
designator R?  ValueDisplayed: 1.84k  (hidden comment: RT0603DRE071K84L)
RES, 1.84 k, 0.5%, 0.1 W, 0603; Manufacturer: Yageo America; CompType: Resistor; Value: 1.84k; Res_ohm: 1840; Value_Code: 1k84; Tolerance_%: 0.5; Power_W: 0.1; Value2: 0.1W; VDC_V: 75; TempCo: 50 ppm/C; SizeArea_mm2: 1.28; SizeX_mm: 1.6; SizeY_mm: 0.8; SizeZ_mm: 1; EIA_Code: E192; U/M: EA; AEC Category: Q200
signal-integrity model Resistor
simulation model Resistor
footprint 0603
footprint 0603M
footprint 0603L
footprint 0603_HV
footprint 0603S
pins: 1, 2

## RT0603DRE071K87L
designator R?  ValueDisplayed: 1.87k  (hidden comment: RT0603DRE071K87L)
RES, 1.87 k, 0.5%, 0.1 W, 0603; Manufacturer: Yageo America; CompType: Resistor; Value: 1.87k; Res_ohm: 1870; Value_Code: 1k87; Tolerance_%: 0.5; Power_W: 0.1; Value2: 0.1W; VDC_V: 75; TempCo: 50 ppm/C; SizeArea_mm2: 1.28; SizeX_mm: 1.6; SizeY_mm: 0.8; SizeZ_mm: 1; EIA_Code: E192; U/M: EA; AEC Category: Q200
signal-integrity model Resistor
simulation model Resistor
footprint 0603
footprint 0603M
footprint 0603L
footprint 0603_HV
footprint 0603S
pins: 1, 2

## RT0603DRE071K89L
designator R?  ValueDisplayed: 1.89k  (hidden comment: RT0603DRE071K89L)
RES, 1.89 k, 0.5%, 0.1 W, 0603; Manufacturer: Yageo America; CompType: Resistor; Value: 1.89k; Res_ohm: 1890; Value_Code: 1k89; Tolerance_%: 0.5; Power_W: 0.1; Value2: 0.1W; VDC_V: 75; TempCo: 50 ppm/C; SizeArea_mm2: 1.28; SizeX_mm: 1.6; SizeY_mm: 0.8; SizeZ_mm: 1; EIA_Code: E192; U/M: EA; AEC Category: Q200
signal-integrity model Resistor
simulation model Resistor
footprint 0603
footprint 0603M
footprint 0603L
footprint 0603_HV
footprint 0603S
pins: 1, 2

## RT0603DRE071K91L
designator R?  ValueDisplayed: 1.91k  (hidden comment: RT0603DRE071K91L)
RES, 1.91 k, 0.5%, 0.1 W, 0603; Manufacturer: Yageo America; CompType: Resistor; Value: 1.91k; Res_ohm: 1910; Value_Code: 1k91; Tolerance_%: 0.5; Power_W: 0.1; Value2: 0.1W; VDC_V: 75; TempCo: 50 ppm/C; SizeArea_mm2: 1.28; SizeX_mm: 1.6; SizeY_mm: 0.8; SizeZ_mm: 1; EIA_Code: E192; U/M: EA; AEC Category: Q200
signal-integrity model Resistor
simulation model Resistor
footprint 0603
footprint 0603M
footprint 0603L
footprint 0603_HV
footprint 0603S
pins: 1, 2

## RT0603DRE071K93L
designator R?  ValueDisplayed: 1.93k  (hidden comment: RT0603DRE071K93L)
RES, 1.93 k, 0.5%, 0.1 W, 0603; Manufacturer: Yageo America; CompType: Resistor; Value: 1.93k; Res_ohm: 1930; Value_Code: 1k93; Tolerance_%: 0.5; Power_W: 0.1; Value2: 0.1W; VDC_V: 75; TempCo: 50 ppm/C; SizeArea_mm2: 1.28; SizeX_mm: 1.6; SizeY_mm: 0.8; SizeZ_mm: 1; EIA_Code: E192; U/M: EA; AEC Category: Q200
signal-integrity model Resistor
simulation model Resistor
footprint 0603
footprint 0603M
footprint 0603L
footprint 0603_HV
footprint 0603S
pins: 1, 2

## RT0603DRE071K96L
designator R?  ValueDisplayed: 1.96k  (hidden comment: RT0603DRE071K96L)
RES, 1.96 k, 0.5%, 0.1 W, 0603; Manufacturer: Yageo America; CompType: Resistor; Value: 1.96k; Res_ohm: 1960; Value_Code: 1k96; Tolerance_%: 0.5; Power_W: 0.1; Value2: 0.1W; VDC_V: 75; TempCo: 50 ppm/C; SizeArea_mm2: 1.28; SizeX_mm: 1.6; SizeY_mm: 0.8; SizeZ_mm: 1; EIA_Code: E192; U/M: EA; AEC Category: Q200
signal-integrity model Resistor
simulation model Resistor
footprint 0603
footprint 0603M
footprint 0603L
footprint 0603_HV
footprint 0603S
pins: 1, 2

## RT0603DRE071K98L
designator R?  ValueDisplayed: 1.98k  (hidden comment: RT0603DRE071K98L)
RES, 1.98 k, 0.5%, 0.1 W, 0603; Manufacturer: Yageo America; CompType: Resistor; Value: 1.98k; Res_ohm: 1980; Value_Code: 1k98; Tolerance_%: 0.5; Power_W: 0.1; Value2: 0.1W; VDC_V: 75; TempCo: 50 ppm/C; SizeArea_mm2: 1.28; SizeX_mm: 1.6; SizeY_mm: 0.8; SizeZ_mm: 1; EIA_Code: E192; U/M: EA; AEC Category: Q200
signal-integrity model Resistor
simulation model Resistor
footprint 0603
footprint 0603M
footprint 0603L
footprint 0603_HV
footprint 0603S
pins: 1, 2

## RT0603DRE071KL
designator R?  ValueDisplayed: 1.00k  (hidden comment: RT0603DRE071KL)
RES, 1.00 k, 0.5%, 0.1 W, 0603; Manufacturer: Yageo America; CompType: Resistor; Value: 1.00k; Res_ohm: 1000; Value_Code: 1k00; Tolerance_%: 0.5; Power_W: 0.1; Value2: 0.1W; VDC_V: 75; TempCo: 50 ppm/C; SizeArea_mm2: 1.28; SizeX_mm: 1.6; SizeY_mm: 0.8; SizeZ_mm: 1; EIA_Code: E192; U/M: EA; AEC Category: Q200
signal-integrity model Resistor
simulation model Resistor
footprint 0603
footprint 0603M
footprint 0603L
footprint 0603_HV
footprint 0603S
pins: 1, 2

## RT0603DRE071R01L
designator R?  ValueDisplayed: 1.01  (hidden comment: RT0603DRE071R01L)
RES, 1.01, 0.5%, 0.1 W, 0603; Manufacturer: Yageo America; CompType: Resistor; Value: 1.01; Value_Code: 1R01; Tolerance_%: 0.5; Power_W: 0.1; Value2: 0.1W; VDC_V: 75; TempCo: 50 ppm/C; SizeArea_mm2: 1.28; SizeX_mm: 1.6; SizeY_mm: 0.8; SizeZ_mm: 1; EIA_Code: E192; U/M: EA; AEC Category: Q200
signal-integrity model Resistor
simulation model Resistor
footprint 0603
footprint 0603M
footprint 0603L
footprint 0603_HV
footprint 0603S
pins: 1, 2

## RT0603DRE071R1L
designator R?  ValueDisplayed: 1.10  (hidden comment: RT0603DRE071R1L)
RES, 1.10, 0.5%, 0.1 W, 0603; Manufacturer: Yageo America; CompType: Resistor; Value: 1.10; Res_ohm: 1.1; Value_Code: 1R10; Tolerance_%: 0.5; Power_W: 0.1; Value2: 0.1W; VDC_V: 75; TempCo: 50 ppm/C; SizeArea_mm2: 1.28; SizeX_mm: 1.6; SizeY_mm: 0.8; SizeZ_mm: 1; EIA_Code: E192; U/M: EA; AEC Category: Q200
signal-integrity model Resistor
simulation model Resistor
footprint 0603
footprint 0603M
footprint 0603L
footprint 0603_HV
footprint 0603S
pins: 1, 2

## RT0603DRE071R02L
designator R?  ValueDisplayed: 1.02  (hidden comment: RT0603DRE071R02L)
RES, 1.02, 0.5%, 0.1 W, 0603; Manufacturer: Yageo America; CompType: Resistor; Value: 1.02; Value_Code: 1R02; Tolerance_%: 0.5; Power_W: 0.1; Value2: 0.1W; VDC_V: 75; TempCo: 50 ppm/C; SizeArea_mm2: 1.28; SizeX_mm: 1.6; SizeY_mm: 0.8; SizeZ_mm: 1; EIA_Code: E192; U/M: EA; AEC Category: Q200
signal-integrity model Resistor
simulation model Resistor
footprint 0603
footprint 0603M
footprint 0603L
footprint 0603_HV
footprint 0603S
pins: 1, 2

## RT0603DRE071R2L
designator R?  ValueDisplayed: 1.20  (hidden comment: RT0603DRE071R2L)
RES, 1.20, 0.5%, 0.1 W, 0603; Manufacturer: Yageo America; CompType: Resistor; Value: 1.20; Res_ohm: 1.2; Value_Code: 1R20; Tolerance_%: 0.5; Power_W: 0.1; Value2: 0.1W; VDC_V: 75; TempCo: 50 ppm/C; SizeArea_mm2: 1.28; SizeX_mm: 1.6; SizeY_mm: 0.8; SizeZ_mm: 1; EIA_Code: E192; U/M: EA; AEC Category: Q200
signal-integrity model Resistor
simulation model Resistor
footprint 0603
footprint 0603M
footprint 0603L
footprint 0603_HV
footprint 0603S
pins: 1, 2

## RT0603DRE071R3L
designator R?  ValueDisplayed: 1.30  (hidden comment: RT0603DRE071R3L)
RES, 1.30, 0.5%, 0.1 W, 0603; Manufacturer: Yageo America; CompType: Resistor; Value: 1.30; Res_ohm: 1.3; Value_Code: 1R30; Tolerance_%: 0.5; Power_W: 0.1; Value2: 0.1W; VDC_V: 75; TempCo: 50 ppm/C; SizeArea_mm2: 1.28; SizeX_mm: 1.6; SizeY_mm: 0.8; SizeZ_mm: 1; EIA_Code: E192; U/M: EA; AEC Category: Q200
signal-integrity model Resistor
simulation model Resistor
footprint 0603
footprint 0603M
footprint 0603L
footprint 0603_HV
footprint 0603S
pins: 1, 2

## RT0603DRE071R04L
designator R?  ValueDisplayed: 1.04  (hidden comment: RT0603DRE071R04L)
RES, 1.04, 0.5%, 0.1 W, 0603; Manufacturer: Yageo America; CompType: Resistor; Value: 1.04; Value_Code: 1R04; Tolerance_%: 0.5; Power_W: 0.1; Value2: 0.1W; VDC_V: 75; TempCo: 50 ppm/C; SizeArea_mm2: 1.28; SizeX_mm: 1.6; SizeY_mm: 0.8; SizeZ_mm: 1; EIA_Code: E192; U/M: EA; AEC Category: Q200
signal-integrity model Resistor
simulation model Resistor
footprint 0603
footprint 0603M
footprint 0603L
footprint 0603_HV
footprint 0603S
pins: 1, 2

## RT0603DRE071R4L
designator R?  ValueDisplayed: 1.40  (hidden comment: RT0603DRE071R4L)
RES, 1.40, 0.5%, 0.1 W, 0603; Manufacturer: Yageo America; CompType: Resistor; Value: 1.40; Res_ohm: 1.4; Value_Code: 1R40; Tolerance_%: 0.5; Power_W: 0.1; Value2: 0.1W; VDC_V: 75; TempCo: 50 ppm/C; SizeArea_mm2: 1.28; SizeX_mm: 1.6; SizeY_mm: 0.8; SizeZ_mm: 1; EIA_Code: E192; U/M: EA; AEC Category: Q200
signal-integrity model Resistor
simulation model Resistor
footprint 0603
footprint 0603M
footprint 0603L
footprint 0603_HV
footprint 0603S
pins: 1, 2

## RT0603DRE071R05L
designator R?  ValueDisplayed: 1.05  (hidden comment: RT0603DRE071R05L)
RES, 1.05, 0.5%, 0.1 W, 0603; Manufacturer: Yageo America; CompType: Resistor; Value: 1.05; Value_Code: 1R05; Tolerance_%: 0.5; Power_W: 0.1; Value2: 0.1W; VDC_V: 75; TempCo: 50 ppm/C; SizeArea_mm2: 1.28; SizeX_mm: 1.6; SizeY_mm: 0.8; SizeZ_mm: 1; EIA_Code: E192; U/M: EA; AEC Category: Q200
signal-integrity model Resistor
simulation model Resistor
footprint 0603
footprint 0603M
footprint 0603L
footprint 0603_HV
footprint 0603S
pins: 1, 2

## RT0603DRE071R5L
designator R?  ValueDisplayed: 1.50  (hidden comment: RT0603DRE071R5L)
RES, 1.50, 0.5%, 0.1 W, 0603; Manufacturer: Yageo America; CompType: Resistor; Value: 1.50; Res_ohm: 1.5; Value_Code: 1R50; Tolerance_%: 0.5; Power_W: 0.1; Value2: 0.1W; VDC_V: 75; TempCo: 50 ppm/C; SizeArea_mm2: 1.28; SizeX_mm: 1.6; SizeY_mm: 0.8; SizeZ_mm: 1; EIA_Code: E192; U/M: EA; AEC Category: Q200
signal-integrity model Resistor
simulation model Resistor
footprint 0603
footprint 0603M
footprint 0603L
footprint 0603_HV
footprint 0603S
pins: 1, 2

## RT0603DRE071R06L
designator R?  ValueDisplayed: 1.06  (hidden comment: RT0603DRE071R06L)
RES, 1.06, 0.5%, 0.1 W, 0603; Manufacturer: Yageo America; CompType: Resistor; Value: 1.06; Value_Code: 1R06; Tolerance_%: 0.5; Power_W: 0.1; Value2: 0.1W; VDC_V: 75; TempCo: 50 ppm/C; SizeArea_mm2: 1.28; SizeX_mm: 1.6; SizeY_mm: 0.8; SizeZ_mm: 1; EIA_Code: E192; U/M: EA; AEC Category: Q200
signal-integrity model Resistor
simulation model Resistor
footprint 0603
footprint 0603M
footprint 0603L
footprint 0603_HV
footprint 0603S
pins: 1, 2

## RT0603DRE071R6L
designator R?  ValueDisplayed: 1.60  (hidden comment: RT0603DRE071R6L)
RES, 1.60, 0.5%, 0.1 W, 0603; Manufacturer: Yageo America; CompType: Resistor; Value: 1.60; Res_ohm: 1.6; Value_Code: 1R60; Tolerance_%: 0.5; Power_W: 0.1; Value2: 0.1W; VDC_V: 75; TempCo: 50 ppm/C; SizeArea_mm2: 1.28; SizeY_mm: 0.8; SizeZ_mm: 1; EIA_Code: E192; U/M: EA; AEC Category: Q200
signal-integrity model Resistor
simulation model Resistor
footprint 0603
footprint 0603M
footprint 0603L
footprint 0603_HV
footprint 0603S
pins: 1, 2

## RT0603DRE071R07L
designator R?  ValueDisplayed: 1.07  (hidden comment: RT0603DRE071R07L)
RES, 1.07, 0.5%, 0.1 W, 0603; Manufacturer: Yageo America; CompType: Resistor; Value: 1.07; Value_Code: 1R07; Tolerance_%: 0.5; Power_W: 0.1; Value2: 0.1W; VDC_V: 75; TempCo: 50 ppm/C; SizeArea_mm2: 1.28; SizeX_mm: 1.6; SizeY_mm: 0.8; SizeZ_mm: 1; EIA_Code: E192; U/M: EA; AEC Category: Q200
signal-integrity model Resistor
simulation model Resistor
footprint 0603
footprint 0603M
footprint 0603L
footprint 0603_HV
footprint 0603S
pins: 1, 2

## RT0603DRE071R8L
designator R?  ValueDisplayed: 1.80  (hidden comment: RT0603DRE071R8L)
RES, 1.80, 0.5%, 0.1 W, 0603; Manufacturer: Yageo America; CompType: Resistor; Value: 1.80; Res_ohm: 1.8; Value_Code: 1R80; Tolerance_%: 0.5; Power_W: 0.1; Value2: 0.1W; VDC_V: 75; TempCo: 50 ppm/C; SizeArea_mm2: 1.28; SizeX_mm: 1.6; SizeY_mm: 0.8; SizeZ_mm: 1; EIA_Code: E192; U/M: EA; AEC Category: Q200
signal-integrity model Resistor
simulation model Resistor
footprint 0603
footprint 0603M
footprint 0603L
footprint 0603_HV
footprint 0603S
pins: 1, 2

## RT0603DRE071R09L
designator R?  ValueDisplayed: 1.09  (hidden comment: RT0603DRE071R09L)
RES, 1.09, 0.5%, 0.1 W, 0603; Manufacturer: Yageo America; CompType: Resistor; Value: 1.09; Value_Code: 1R09; Tolerance_%: 0.5; Power_W: 0.1; Value2: 0.1W; VDC_V: 75; TempCo: 50 ppm/C; SizeArea_mm2: 1.28; SizeX_mm: 1.6; SizeY_mm: 0.8; SizeZ_mm: 1; EIA_Code: E192; U/M: EA; AEC Category: Q200
signal-integrity model Resistor
simulation model Resistor
footprint 0603
footprint 0603M
footprint 0603L
footprint 0603_HV
footprint 0603S
pins: 1, 2

## RT0603DRE071R11L
designator R?  ValueDisplayed: 1.11  (hidden comment: RT0603DRE071R11L)
RES, 1.11, 0.5%, 0.1 W, 0603; Manufacturer: Yageo America; CompType: Resistor; Value: 1.11; Value_Code: 1R11; Tolerance_%: 0.5; Power_W: 0.1; Value2: 0.1W; VDC_V: 75; TempCo: 50 ppm/C; SizeArea_mm2: 1.28; SizeX_mm: 1.6; SizeY_mm: 0.8; SizeZ_mm: 1; EIA_Code: E192; U/M: EA; AEC Category: Q200
signal-integrity model Resistor
simulation model Resistor
footprint 0603
footprint 0603M
footprint 0603L
footprint 0603_HV
footprint 0603S
pins: 1, 2

## RT0603DRE071R13L
designator R?  ValueDisplayed: 1.13  (hidden comment: RT0603DRE071R13L)
RES, 1.13, 0.5%, 0.1 W, 0603; Manufacturer: Yageo America; CompType: Resistor; Value: 1.13; Value_Code: 1R13; Tolerance_%: 0.5; Power_W: 0.1; Value2: 0.1W; VDC_V: 75; TempCo: 50 ppm/C; SizeArea_mm2: 1.28; SizeX_mm: 1.6; SizeY_mm: 0.8; SizeZ_mm: 1; EIA_Code: E192; U/M: EA; AEC Category: Q200
signal-integrity model Resistor
simulation model Resistor
footprint 0603
footprint 0603M
footprint 0603L
footprint 0603_HV
footprint 0603S
pins: 1, 2

## RT0603DRE071R14L
designator R?  ValueDisplayed: 1.14  (hidden comment: RT0603DRE071R14L)
RES, 1.14, 0.5%, 0.1 W, 0603; Manufacturer: Yageo America; CompType: Resistor; Value: 1.14; Value_Code: 1R14; Tolerance_%: 0.5; Power_W: 0.1; Value2: 0.1W; VDC_V: 75; TempCo: 50 ppm/C; SizeArea_mm2: 1.28; SizeX_mm: 1.6; SizeY_mm: 0.8; SizeZ_mm: 1; EIA_Code: E192; U/M: EA; AEC Category: Q200
signal-integrity model Resistor
simulation model Resistor
footprint 0603
footprint 0603M
footprint 0603L
footprint 0603_HV
footprint 0603S
pins: 1, 2

## RT0603DRE071R15L
designator R?  ValueDisplayed: 1.15  (hidden comment: RT0603DRE071R15L)
RES, 1.15, 0.5%, 0.1 W, 0603; Manufacturer: Yageo America; CompType: Resistor; Value: 1.15; Value_Code: 1R15; Tolerance_%: 0.5; Power_W: 0.1; Value2: 0.1W; VDC_V: 75; TempCo: 50 ppm/C; SizeArea_mm2: 1.28; SizeX_mm: 1.6; SizeY_mm: 0.8; SizeZ_mm: 1; EIA_Code: E192; U/M: EA; AEC Category: Q200
signal-integrity model Resistor
simulation model Resistor
footprint 0603
footprint 0603M
footprint 0603L
footprint 0603_HV
footprint 0603S
pins: 1, 2

## RT0603DRE071R17L
designator R?  ValueDisplayed: 1.17  (hidden comment: RT0603DRE071R17L)
RES, 1.17, 0.5%, 0.1 W, 0603; Manufacturer: Yageo America; CompType: Resistor; Value: 1.17; Value_Code: 1R17; Tolerance_%: 0.5; Power_W: 0.1; Value2: 0.1W; VDC_V: 75; TempCo: 50 ppm/C; SizeArea_mm2: 1.28; SizeX_mm: 1.6; SizeY_mm: 0.8; SizeZ_mm: 1; EIA_Code: E192; U/M: EA; AEC Category: Q200
signal-integrity model Resistor
simulation model Resistor
footprint 0603
footprint 0603M
footprint 0603L
footprint 0603_HV
footprint 0603S
pins: 1, 2

## RT0603DRE071R18L
designator R?  ValueDisplayed: 1.18  (hidden comment: RT0603DRE071R18L)
RES, 1.18, 0.5%, 0.1 W, 0603; Manufacturer: Yageo America; CompType: Resistor; Value: 1.18; Value_Code: 1R18; Tolerance_%: 0.5; Power_W: 0.1; Value2: 0.1W; VDC_V: 75; TempCo: 50 ppm/C; SizeArea_mm2: 1.28; SizeX_mm: 1.6; SizeY_mm: 0.8; SizeZ_mm: 1; EIA_Code: E192; U/M: EA; AEC Category: Q200
signal-integrity model Resistor
simulation model Resistor
footprint 0603
footprint 0603M
footprint 0603L
footprint 0603_HV
footprint 0603S
pins: 1, 2

## RT0603DRE071R21L
designator R?  ValueDisplayed: 1.21  (hidden comment: RT0603DRE071R21L)
RES, 1.21, 0.5%, 0.1 W, 0603; Manufacturer: Yageo America; CompType: Resistor; Value: 1.21; Value_Code: 1R21; Tolerance_%: 0.5; Power_W: 0.1; Value2: 0.1W; VDC_V: 75; TempCo: 50 ppm/C; SizeArea_mm2: 1.28; SizeX_mm: 1.6; SizeY_mm: 0.8; SizeZ_mm: 1; EIA_Code: E192; U/M: EA; AEC Category: Q200
signal-integrity model Resistor
simulation model Resistor
footprint 0603
footprint 0603M
footprint 0603L
footprint 0603_HV
footprint 0603S
pins: 1, 2

## RT0603DRE071R23L
designator R?  ValueDisplayed: 1.23  (hidden comment: RT0603DRE071R23L)
RES, 1.23, 0.5%, 0.1 W, 0603; Manufacturer: Yageo America; CompType: Resistor; Value: 1.23; Value_Code: 1R23; Tolerance_%: 0.5; Power_W: 0.1; Value2: 0.1W; VDC_V: 75; TempCo: 50 ppm/C; SizeArea_mm2: 1.28; SizeX_mm: 1.6; SizeY_mm: 0.8; SizeZ_mm: 1; EIA_Code: E192; U/M: EA; AEC Category: Q200
signal-integrity model Resistor
simulation model Resistor
footprint 0603
footprint 0603M
footprint 0603L
footprint 0603_HV
footprint 0603S
pins: 1, 2

## RT0603DRE071R24L
designator R?  ValueDisplayed: 1.24  (hidden comment: RT0603DRE071R24L)
RES, 1.24, 0.5%, 0.1 W, 0603; Manufacturer: Yageo America; CompType: Resistor; Value: 1.24; Value_Code: 1R24; Tolerance_%: 0.5; Power_W: 0.1; Value2: 0.1W; VDC_V: 75; TempCo: 50 ppm/C; SizeArea_mm2: 1.28; SizeX_mm: 1.6; SizeY_mm: 0.8; SizeZ_mm: 1; EIA_Code: E192; U/M: EA; AEC Category: Q200
signal-integrity model Resistor
simulation model Resistor
footprint 0603
footprint 0603M
footprint 0603L
footprint 0603_HV
footprint 0603S
pins: 1, 2

## RT0603DRE071R26L
designator R?  ValueDisplayed: 1.26  (hidden comment: RT0603DRE071R26L)
RES, 1.26, 0.5%, 0.1 W, 0603; Manufacturer: Yageo America; CompType: Resistor; Value: 1.26; Value_Code: 1R26; Tolerance_%: 0.5; Power_W: 0.1; Value2: 0.1W; VDC_V: 75; TempCo: 50 ppm/C; SizeArea_mm2: 1.28; SizeX_mm: 1.6; SizeY_mm: 0.8; SizeZ_mm: 1; EIA_Code: E192; U/M: EA; AEC Category: Q200
signal-integrity model Resistor
simulation model Resistor
footprint 0603
footprint 0603M
footprint 0603L
footprint 0603_HV
footprint 0603S
pins: 1, 2

## RT0603DRE071R27L
designator R?  ValueDisplayed: 1.27  (hidden comment: RT0603DRE071R27L)
RES, 1.27, 0.5%, 0.1 W, 0603; Manufacturer: Yageo America; CompType: Resistor; Value: 1.27; Value_Code: 1R27; Tolerance_%: 0.5; Power_W: 0.1; Value2: 0.1W; VDC_V: 75; TempCo: 50 ppm/C; SizeArea_mm2: 1.28; SizeX_mm: 1.6; SizeY_mm: 0.8; SizeZ_mm: 1; EIA_Code: E192; U/M: EA; AEC Category: Q200
signal-integrity model Resistor
simulation model Resistor
footprint 0603
footprint 0603M
footprint 0603L
footprint 0603_HV
footprint 0603S
pins: 1, 2

## RT0603DRE071R29L
designator R?  ValueDisplayed: 1.29  (hidden comment: RT0603DRE071R29L)
RES, 1.29, 0.5%, 0.1 W, 0603; Manufacturer: Yageo America; CompType: Resistor; Value: 1.29; Value_Code: 1R29; Tolerance_%: 0.5; Power_W: 0.1; Value2: 0.1W; VDC_V: 75; TempCo: 50 ppm/C; SizeArea_mm2: 1.28; SizeX_mm: 1.6; SizeY_mm: 0.8; SizeZ_mm: 1; EIA_Code: E192; U/M: EA; AEC Category: Q200
signal-integrity model Resistor
simulation model Resistor
footprint 0603
footprint 0603M
footprint 0603L
footprint 0603_HV
footprint 0603S
pins: 1, 2

## RT0603DRE071R32L
designator R?  ValueDisplayed: 1.32  (hidden comment: RT0603DRE071R32L)
RES, 1.32, 0.5%, 0.1 W, 0603; Manufacturer: Yageo America; CompType: Resistor; Value: 1.32; Value_Code: 1R32; Tolerance_%: 0.5; Power_W: 0.1; Value2: 0.1W; VDC_V: 75; TempCo: 50 ppm/C; SizeArea_mm2: 1.28; SizeX_mm: 1.6; SizeY_mm: 0.8; SizeZ_mm: 1; EIA_Code: E192; U/M: EA; AEC Category: Q200
signal-integrity model Resistor
simulation model Resistor
footprint 0603
footprint 0603M
footprint 0603L
footprint 0603_HV
footprint 0603S
pins: 1, 2

## RT0603DRE071R33L
designator R?  ValueDisplayed: 1.33  (hidden comment: RT0603DRE071R33L)
RES, 1.33, 0.5%, 0.1 W, 0603; Manufacturer: Yageo America; CompType: Resistor; Value: 1.33; Value_Code: 1R33; Tolerance_%: 0.5; Power_W: 0.1; Value2: 0.1W; VDC_V: 75; TempCo: 50 ppm/C; SizeArea_mm2: 1.28; SizeX_mm: 1.6; SizeY_mm: 0.8; SizeZ_mm: 1; EIA_Code: E192; U/M: EA; AEC Category: Q200
signal-integrity model Resistor
simulation model Resistor
footprint 0603
footprint 0603M
footprint 0603L
footprint 0603_HV
footprint 0603S
pins: 1, 2

## RT0603DRE071R35L
designator R?  ValueDisplayed: 1.35  (hidden comment: RT0603DRE071R35L)
RES, 1.35, 0.5%, 0.1 W, 0603; Manufacturer: Yageo America; CompType: Resistor; Value: 1.35; Value_Code: 1R35; Tolerance_%: 0.5; Power_W: 0.1; Value2: 0.1W; VDC_V: 75; TempCo: 50 ppm/C; SizeArea_mm2: 1.28; SizeX_mm: 1.6; SizeY_mm: 0.8; SizeZ_mm: 1; EIA_Code: E192; U/M: EA; AEC Category: Q200
signal-integrity model Resistor
simulation model Resistor
footprint 0603
footprint 0603M
footprint 0603L
footprint 0603_HV
footprint 0603S
pins: 1, 2

## RT0603DRE071R37L
designator R?  ValueDisplayed: 1.37  (hidden comment: RT0603DRE071R37L)
RES, 1.37, 0.5%, 0.1 W, 0603; Manufacturer: Yageo America; CompType: Resistor; Value: 1.37; Value_Code: 1R37; Tolerance_%: 0.5; Power_W: 0.1; Value2: 0.1W; VDC_V: 75; TempCo: 50 ppm/C; SizeArea_mm2: 1.28; SizeX_mm: 1.6; SizeY_mm: 0.8; SizeZ_mm: 1; EIA_Code: E192; U/M: EA; AEC Category: Q200
signal-integrity model Resistor
simulation model Resistor
footprint 0603
footprint 0603M
footprint 0603L
footprint 0603_HV
footprint 0603S
pins: 1, 2

## RT0603DRE071R38L
designator R?  ValueDisplayed: 1.38  (hidden comment: RT0603DRE071R38L)
RES, 1.38, 0.5%, 0.1 W, 0603; Manufacturer: Yageo America; CompType: Resistor; Value: 1.38; Value_Code: 1R38; Tolerance_%: 0.5; Power_W: 0.1; Value2: 0.1W; VDC_V: 75; TempCo: 50 ppm/C; SizeArea_mm2: 1.28; SizeX_mm: 1.6; SizeY_mm: 0.8; SizeZ_mm: 1; EIA_Code: E192; U/M: EA; AEC Category: Q200
signal-integrity model Resistor
simulation model Resistor
footprint 0603
footprint 0603M
footprint 0603L
footprint 0603_HV
footprint 0603S
pins: 1, 2

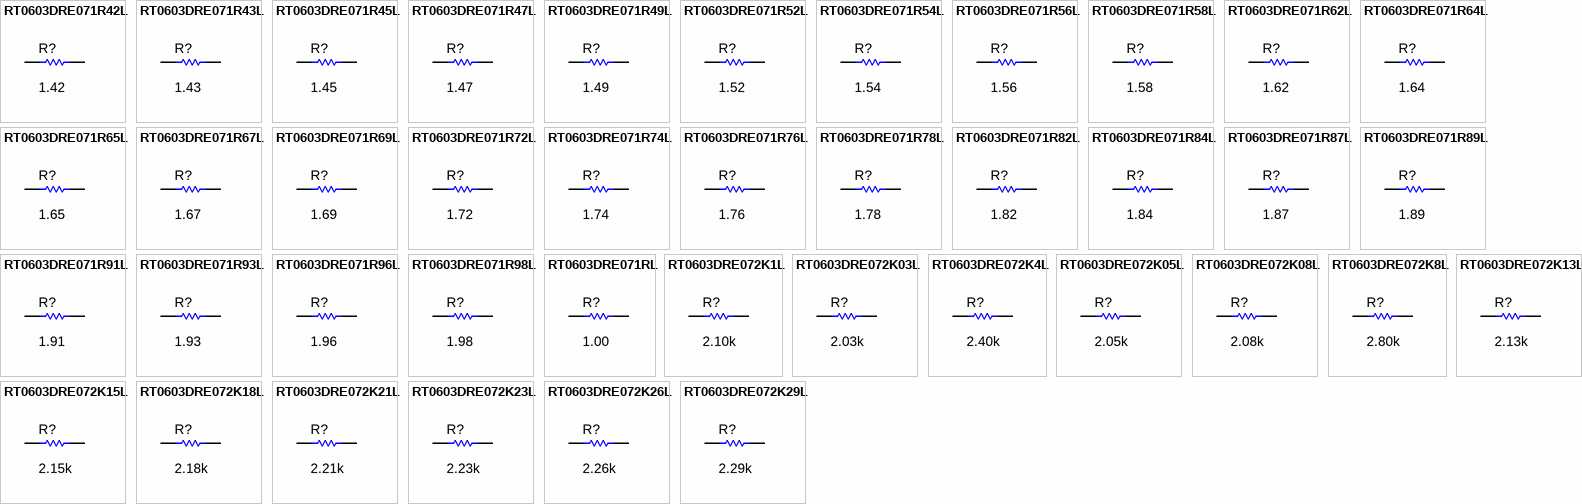
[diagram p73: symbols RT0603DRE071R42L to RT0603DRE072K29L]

## RT0603DRE071R42L
designator R?  ValueDisplayed: 1.42  (hidden comment: RT0603DRE071R42L)
RES, 1.42, 0.5%, 0.1 W, 0603; Manufacturer: Yageo America; CompType: Resistor; Value: 1.42; Value_Code: 1R42; Tolerance_%: 0.5; Power_W: 0.1; Value2: 0.1W; VDC_V: 75; TempCo: 50 ppm/C; SizeArea_mm2: 1.28; SizeX_mm: 1.6; SizeY_mm: 0.8; SizeZ_mm: 1; EIA_Code: E192; U/M: EA; AEC Category: Q200
signal-integrity model Resistor
simulation model Resistor
footprint 0603
footprint 0603M
footprint 0603L
footprint 0603_HV
footprint 0603S
pins: 1, 2

## RT0603DRE071R43L
designator R?  ValueDisplayed: 1.43  (hidden comment: RT0603DRE071R43L)
RES, 1.43, 0.5%, 0.1 W, 0603; Manufacturer: Yageo America; CompType: Resistor; Value: 1.43; Value_Code: 1R43; Tolerance_%: 0.5; Power_W: 0.1; Value2: 0.1W; VDC_V: 75; TempCo: 50 ppm/C; SizeArea_mm2: 1.28; SizeX_mm: 1.6; SizeY_mm: 0.8; SizeZ_mm: 1; EIA_Code: E192; U/M: EA; AEC Category: Q200
signal-integrity model Resistor
simulation model Resistor
footprint 0603
footprint 0603M
footprint 0603L
footprint 0603_HV
footprint 0603S
pins: 1, 2

## RT0603DRE071R45L
designator R?  ValueDisplayed: 1.45  (hidden comment: RT0603DRE071R45L)
RES, 1.45, 0.5%, 0.1 W, 0603; Manufacturer: Yageo America; CompType: Resistor; Value: 1.45; Value_Code: 1R45; Tolerance_%: 0.5; Power_W: 0.1; Value2: 0.1W; VDC_V: 75; TempCo: 50 ppm/C; SizeArea_mm2: 1.28; SizeX_mm: 1.6; SizeY_mm: 0.8; SizeZ_mm: 1; EIA_Code: E192; U/M: EA; AEC Category: Q200
signal-integrity model Resistor
simulation model Resistor
footprint 0603
footprint 0603M
footprint 0603L
footprint 0603_HV
footprint 0603S
pins: 1, 2

## RT0603DRE071R47L
designator R?  ValueDisplayed: 1.47  (hidden comment: RT0603DRE071R47L)
RES, 1.47, 0.5%, 0.1 W, 0603; Manufacturer: Yageo America; CompType: Resistor; Value: 1.47; Value_Code: 1R47; Tolerance_%: 0.5; Power_W: 0.1; Value2: 0.1W; VDC_V: 75; TempCo: 50 ppm/C; SizeArea_mm2: 1.28; SizeX_mm: 1.6; SizeY_mm: 0.8; SizeZ_mm: 1; EIA_Code: E192; U/M: EA; AEC Category: Q200
signal-integrity model Resistor
simulation model Resistor
footprint 0603
footprint 0603M
footprint 0603L
footprint 0603_HV
footprint 0603S
pins: 1, 2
